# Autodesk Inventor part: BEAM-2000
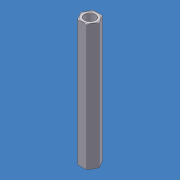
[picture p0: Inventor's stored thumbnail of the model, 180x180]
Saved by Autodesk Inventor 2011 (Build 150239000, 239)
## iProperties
Created: 2007-08
Part Number: BEAM-2000
Material: Aluminum-6061
Document SubType Name: Modeling
Density: 2.71 g/cm^3
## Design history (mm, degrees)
feature "Base1"
body "Solid1"
